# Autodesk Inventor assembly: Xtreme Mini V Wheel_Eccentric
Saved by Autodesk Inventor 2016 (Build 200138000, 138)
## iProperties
Created: 2015-11
Part Number: Xtreme Mini V Wheel_Eccentric
Document SubType Name: Assembly
Designer: John
Author: John
Revision Number: ANY
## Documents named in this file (6)
- D:\3D Printer Designs\John Ledden Designs\DLP Printer\STEP Parts Library 1.1\Assemblies\C-Beam Linear Actuator\Xtreme Mini V Wheel_Eccentric.iam
- D:\3D Printer Designs\John Ledden Designs\DLP Printer\STEP Parts Library 1.1\Assemblies\C-Beam Linear Actuator\Xtreme Mini V Wheel.ipt
- D:\3D Printer Designs\John Ledden Designs\DLP Printer\STEP Parts Library 1.1\Assemblies\C-Beam Linear Actuator\Ball Bearing 5 x 10 x 4.2.ipt
- D:\3D Printer Designs\John Ledden Designs\DLP Printer\STEP Parts Library 1.1\Assemblies\C-Beam Linear Actuator\Precision Shim 8 x 5 x 1.ipt
- D:\3D Printer Designs\John Ledden Designs\DLP Printer\STEP Parts Library 1.1\Assemblies\C-Beam Linear Actuator\Nylon Insert Lock Nut M5.ipt
- D:\3D Printer Designs\John Ledden Designs\DLP Printer\STEP Parts Library 1.1\Assemblies\C-Beam Linear Actuator\Mini Eccentric Spacer 6mm.ipt
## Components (7 placed, 7 different names)
1. Xtreme Mini V Wheel_41
2. Ball Bearing 5 x 10 x 4.2_42
3. Ball Bearing 5 x 10 x 4.2_43
4. Precision Shim 8 x 5 x 1_44
5. Precision Shim 8 x 5 x 1_45
6. Nylon Insert Lock Nut M5_46
7. Mini Eccentric Spacer 6mm_47
